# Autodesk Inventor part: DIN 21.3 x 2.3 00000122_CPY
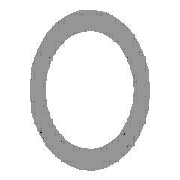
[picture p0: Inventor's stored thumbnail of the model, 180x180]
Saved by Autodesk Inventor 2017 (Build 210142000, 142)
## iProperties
Created: 2017-11
Part Number: DIN 21.3 x 2.3 00000122_CPY
Material: Steel, Mild
Description: Pipe
Document SubType Name: Modeling
Standard: DIN
Designer: iusti
Standard Revision: 2006-07
Standards Organization: DIN
Language: en-US
Size Designation: 21.3 x 2.3
Categories: <MemberInstance><Categories><Category DisplayName="Structural Shapes" InternalName="089c4875-fa83-4c05-b084-43b9cc11f5ed" Mnemonic="GRDR"><CategoryParameter Dis
Stock Number: 21.3 x 2.3
Density: 7.85 g/cm^3
Appearance: Semi-Polished
_CCFamilyMember: 1
_CCFamilyDisplayName: DIN EN 10210-2 - Pipe
_FrameMemberDoc: Frame Member File
_Version: 15.0.0
_GetPNFromCC: 1
IsCustomPart: 1
Author: iusti
G_L: 500.000 mm
G_W: 21.300 mm
G_H: 21.300 mm
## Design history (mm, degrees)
node "Start plane"
node "End plane"
sketch "Sketch"
  geometry: C1 r 8.35 at (0, 0); C2 r 10.65 at (0, 0); 2 further points
  constraints: 3 coincident, 2 centre point
  dimensions: "d0" = 21.3 diameter of C2 (= G_H); "d1" = 2.3 radial gap between concentric circles of C2 C1 (= G_T)
extrude "Body" new body sketch "Sketch" stored distance "d2" = 500 (= G_L); taper "d3" = 0 deg
node "Driven Length"
  sketch "Sketch3"
    geometry: L1 (0, 0)-(10, 0) reference
    constraints: 2 end point, 1 horizontal
  workplane "Work Plane3"
  sketch "Sketch4"
    geometry: L1 (-2, 0)-(12, 0) reference; L2 (-2, 500)-(12, 500) reference
    dimensions: "d7" = 500 distance between parallel lines of L1 L2 (derived)
body "Solid1"
other parameters: "G_H" = 21.3 [user parameter; used in 1 equation term], "G_T" = 2.3 [user parameter; used in 1 equation term], "G_L" = 500 (= d7) [user parameter; used in 1 equation term], "G_OFFSET_START" = 0 [user parameter; used in 1 equation term], "G_OFFSET_END" = 0 [user parameter; used in 1 equation term], "d4" = 0 (computed from G_OFFSET_START), "d6" = 90 deg
